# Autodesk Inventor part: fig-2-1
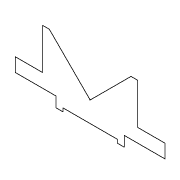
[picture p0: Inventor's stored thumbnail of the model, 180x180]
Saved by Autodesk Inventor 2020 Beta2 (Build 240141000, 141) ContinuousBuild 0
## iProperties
Created: 2011-06
Part Number: fig-2-1
Material: Generic
Document SubType Name: Modeling
Designer: CadCim
Density: 1 g/cm^3
Appearance: Default
Author: CadCim
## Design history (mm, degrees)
sketch "Sketch1"
  geometry: L1 (2, -1.75)-(2.5, -1.75); L2 (-2.5, -1.75)-(-2, -1.75); L3 (-2, -1.75)-(-2, -2); L4 (-2.5, -2.5)-(-2.5, -1.75); L5 (-3, -6.5)-(-3.5, -6.5); L6 (-3.5, -6.5)-(-3.5, -3.5); L7 (-5.5, -2.5)-(-2.5, -2.5); L8 (-5.5, -3.5)-(-5.5, -2.5); L9 (-3.5, -3.5)-(-5.5, -3.5); L10 (0, -3.5)-(-3, -6.5); L11 (-2, -2)-(2, -2); L12 (3, -6.5)-(0, -3.5); L13 (2, -2)-(2, -1.75); L14 (2.5, -1.75)-(2.5, -2.5); L15 (3.5, -6.5)-(3, -6.5); L16 (3.5, -3.5)-(3.5, -6.5); L17 (5.5, -3.5)-(3.5, -3.5); L18 (2.5, -2.5)-(5.5, -2.5); L19 (5.5, -2.5)-(5.5, -3.5); 1 further point
  constraints: 38 end point
